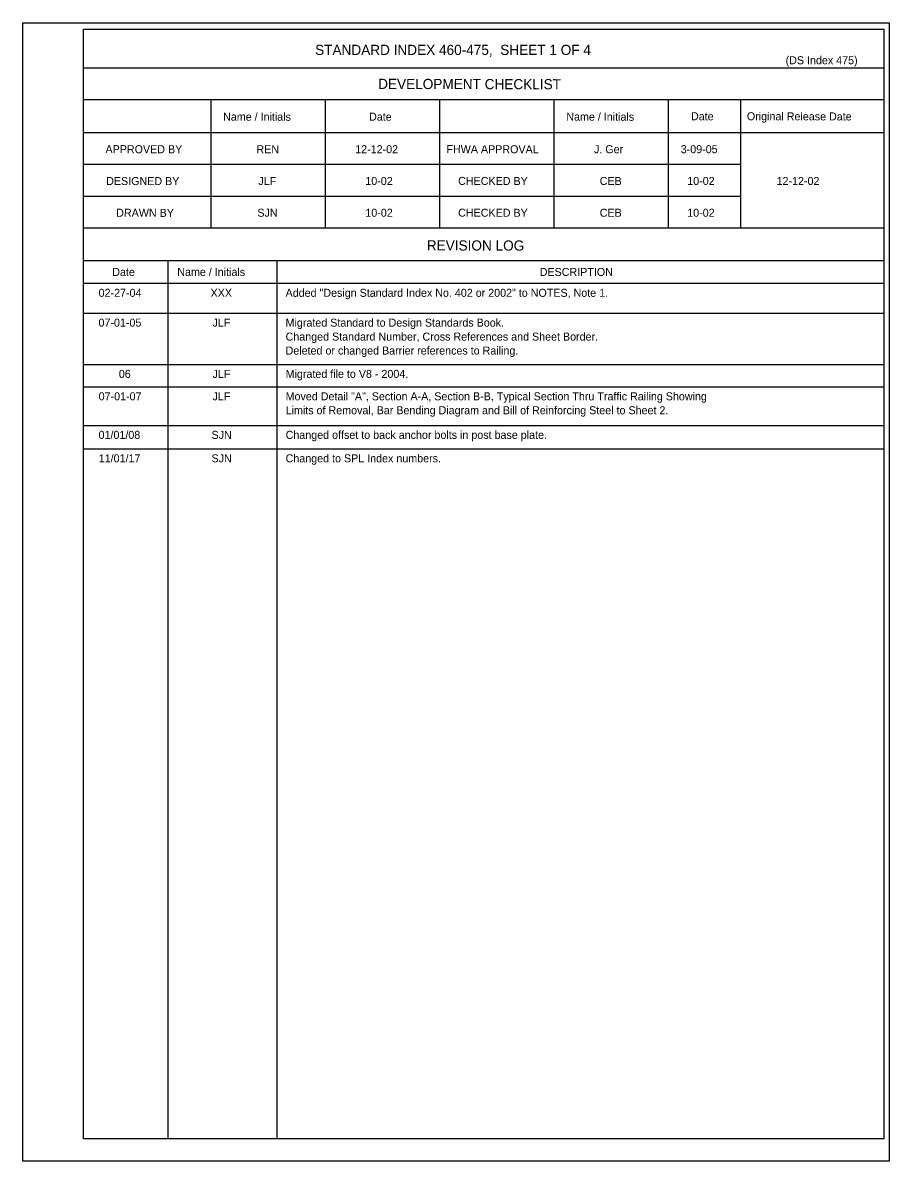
# Model space of a CAD drawing. Extents: x 21516.9 to 21589, y 56154.7 to 56194.3.
# Drawn here: x 21567.19 to 21589, y 56162.34 to 56191 of the extents above; entities that cross this region are included whole.
import ezdxf

# ---------------------------------------------------------------- set-up
doc = ezdxf.new("R2010")
doc.units = 0
for name, color, linetype in [('PlotBorder_dp', 7, 'Continuous'), ('SheetBorder_dp', 7, 'Continuous'), ('SheetLines_dp', 7, 'Continuous')]:
    doc.layers.add(name, color=color, linetype=linetype)

msp = doc.modelspace()

# ---------------------------------------------------------------- linework, layer by layer
at = {"layer": 'PlotBorder_dp'}
for p, q in [((21568.718, 56183.689), (21588.865, 56183.689)), ((21568.719, 56182.398), (21588.865, 56182.398)), ((21568.719, 56181.834), (21588.865, 56181.834)), ((21568.719, 56180.863), (21588.865, 56180.863)), ((21568.719, 56180.272), (21588.865, 56180.272)), ((21567.188, 56162.336), (21567.188, 56162.336))]:
    msp.add_line(p, q, dxfattribs=at)
msp.add_lwpolyline([(21567.188, 56191.002), (21589.001, 56191.002), (21589.001, 56162.336), (21567.188, 56162.336)], close=True, dxfattribs=at)
at = {"layer": 'SheetLines_dp'}
for p, q in [((21588.865, 56189.859), (21568.718, 56189.859)), ((21588.865, 56189.059), (21568.718, 56189.059)), ((21571.918, 56189.059), (21571.918, 56185.831)), ((21574.798, 56189.059), (21574.798, 56185.831)), ((21577.678, 56189.059), (21577.678, 56185.831)), ((21580.558, 56189.059), (21580.558, 56185.831)), ((21583.438, 56189.059), (21583.438, 56185.831)), ((21585.253, 56189.059), (21585.253, 56185.831)), ((21588.865, 56188.231), (21568.718, 56188.231)), ((21585.253, 56187.431), (21568.718, 56187.431)), ((21585.253, 56186.631), (21568.718, 56186.631)), ((21588.865, 56185.831), (21568.718, 56185.831)), ((21588.865, 56185.004), (21568.718, 56185.004)), ((21570.838, 56185.004), (21570.838, 56162.897)), ((21573.581, 56185.004), (21573.581, 56162.897)), ((21588.865, 56184.44), (21568.718, 56184.44))]:
    msp.add_line(p, q, dxfattribs=at)
msp.add_lwpolyline([(21568.718, 56190.84), (21588.865, 56190.84), (21588.865, 56162.897), (21568.718, 56162.897)], close=True, dxfattribs=at)

# ---------------------------------------------------------------- texts
at = {"layer": 'SheetBorder_dp'}
for s, height, p in [('STANDARD INDEX 460-475,  SHEET 1 OF 4', 0.256, (21574.547, 56190.192)), ('(DS Index 475)', 0.2016, (21586.392, 56189.958)), ('REN', 0.2016, (21573.07, 56187.718)), ('12-12-02', 0.2016, (21575.557, 56187.718)), ('J. Ger', 0.2016, (21581.568, 56187.718)), ('3-09-05', 0.2016, (21583.752, 56187.718)), ('JLF', 0.2016, (21573.118, 56186.918)), ('10-02', 0.2016, (21575.812, 56186.918)), ('CEB', 0.2016, (21581.712, 56186.918)), ('10-02', 0.2016, (21583.916, 56186.918)), ('12-12-02', 0.2016, (21586.165, 56186.918)), ('SJN', 0.2016, (21573.093, 56186.118)), ('10-02', 0.2016, (21575.812, 56186.118)), ('CEB', 0.2016, (21581.712, 56186.118)), ('10-02', 0.2016, (21583.916, 56186.118)), ('DESCRIPTION', 0.2016, (21580.202, 56184.627)), ('02-27-04', 0.2016, (21569.097, 56184.102)), ('XXX', 0.2016, (21571.915, 56184.102)), ('Added "Design Standard Index No. 402 or 2002" to NOTES, Note 1. ', 0.2016, (21573.804, 56184.102)), ('07-01-05', 0.2016, (21569.094, 56183.351)), ('JLF', 0.2016, (21571.965, 56183.351)), ('Migrated Standard to Design Standards Book.', 0.2016, (21573.804, 56183.351)), ('Changed Standard Number, Cross References and Sheet Border.', 0.2016, (21573.804, 56182.999)), ('Deleted or changed Barrier references to Railing.', 0.2016, (21573.804, 56182.648)), ('06', 0.2016, (21569.606, 56182.06)), ('JLF', 0.2016, (21571.965, 56182.06)), ('Migrated file to V8 - 2004.', 0.2016, (21573.805, 56182.06)), ('07-01-07', 0.2016, (21569.098, 56181.496)), ('JLF', 0.2016, (21571.965, 56181.496)), ('Moved Detail "A", Section A-A, Section B-B, Typical Section Thru Traffic Railing Showing ', 0.2016, (21573.805, 56181.496)), ('Limits of Removal, Bar Bending Diagram and Bill of Reinforcing Steel to Sheet 2.', 0.2016, (21573.805, 56181.145)), ('01/01/08', 0.2016, (21569.096, 56180.525)), ('SJN', 0.2016, (21571.94, 56180.525)), ('Changed offset to back anchor bolts in post base plate.', 0.2016, (21573.805, 56180.525)), ('11/01/17', 0.2016, (21569.1, 56179.934)), ('SJN', 0.2016, (21571.94, 56179.934)), ('Changed to SPL Index numbers.', 0.2016, (21573.805, 56179.934))]:
    msp.add_text(s, height=height, dxfattribs=at).set_placement(p)
for s, height, p in [('DEVELOPMENT CHECKLIST', 0.256, (21576.134, 56189.336)), ('Name / Initials', 0.2016, (21572.231, 56188.538)), ('Date', 0.2016, (21575.905, 56188.537)), ('Name / Initials', 0.2016, (21580.871, 56188.538)), ('Date', 0.2016, (21584.01, 56188.548)), ('Original Release Date', 0.2016, (21585.417, 56188.548)), ('APPROVED BY', 0.2016, (21569.27, 56187.72)), ('FHWA APPROVAL', 0.2016, (21577.853, 56187.72)), ('DESIGNED BY', 0.2016, (21569.287, 56186.918)), ('CHECKED BY', 0.2016, (21578.148, 56186.92)), ('DRAWN BY', 0.2016, (21569.54, 56186.118)), ('CHECKED BY', 0.2016, (21578.148, 56186.12)), ('REVISION LOG', 0.256, (21577.359, 56185.27)), ('Name / Initials', 0.2016, (21571.077, 56184.629)), ('Date', 0.2016, (21569.44, 56184.627))]:
    msp.add_text(s, height=height, rotation=359.8756, dxfattribs=at).set_placement(p)

doc.saveas('drawing.dxf')
